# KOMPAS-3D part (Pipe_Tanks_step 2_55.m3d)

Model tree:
1. X Axis
2. Y Axis
3. Z Axis  (labels: Pipe Dn 50)
     Òîëùèíà ñòåíêè 1 = 1

Referenced files in C:\Documents and Settings\kashirsky\Мои документы\Camtasia Studio\Pipelines3D\Tanks\: Tanks_step 2.a3d
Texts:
  Pipe Dn 50
  Steel ASTM A295
  Three Point Plane
  Plane at Angle
  Line and Point Plane
  Axis through Two Vertices
  Axis of Feature
  Axis of Conical Surface
  Axis through Edge
  Trim by Surface
  Trim by Sketch
  Feature with No History
  Intersection Axis of Two Planes
  Two Line Plane
  Line and Face Plane
  Bend by line
  Hole in sheet body
  Cut in sheet body
  Point in CM
  Linear Dimension from Line to Point
  Surface Finish Symbol
  Geometric Tolerance Symbol
  Leader #1
  Leader #2
  Leader #3
  Shape Deviations and Datum
  Node point number
  Mark of coordination axis
  Node point designation
  Mark/Reference designation with leader
  Mark/reference designation on line
  Mark/Reference designation without leader
  Plane of section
